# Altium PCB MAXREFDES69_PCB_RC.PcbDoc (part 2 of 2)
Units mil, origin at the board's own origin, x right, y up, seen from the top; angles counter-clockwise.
Board outline 2598.42 x 2244.09 mil, 6 copper layers (Top Layer, Mid-Layer 1, Mid-Layer 2, Mid-Layer 3, Mid-Layer 4, Bottom Layer); 103 components, 84 nets, 415 pads, 171 vias.
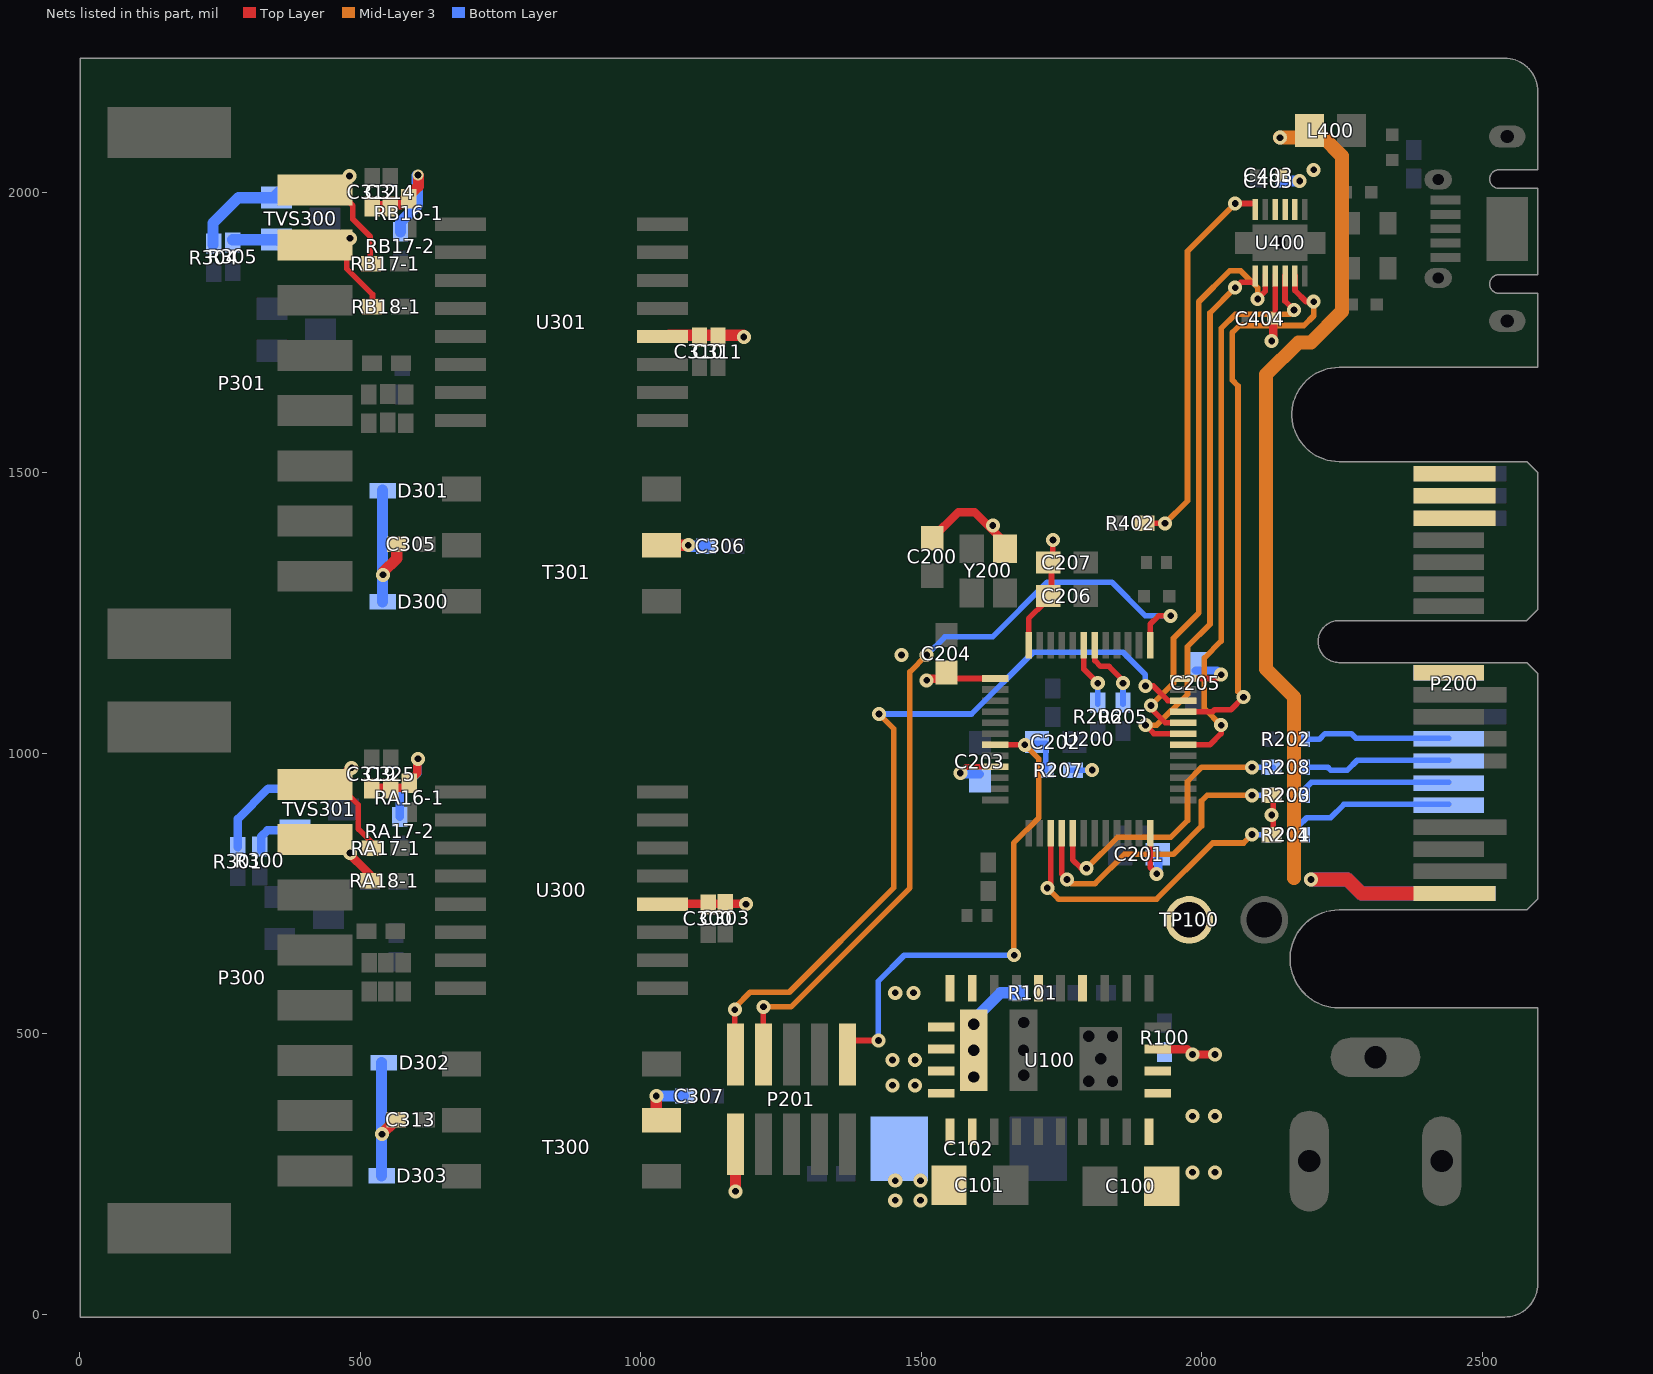
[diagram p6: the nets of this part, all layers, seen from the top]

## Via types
v1: diameter 25, hole 12, Top Layer to Bottom Layer, 164 vias
v2: diameter 20, hole 12, Top Layer to Bottom Layer, 3 vias
v3: diameter 25, hole 12, Top Layer to Bottom Layer, tented top, 3 vias
v4: diameter 25, hole 12, Top Layer to Bottom Layer, tented bottom, 1 vias

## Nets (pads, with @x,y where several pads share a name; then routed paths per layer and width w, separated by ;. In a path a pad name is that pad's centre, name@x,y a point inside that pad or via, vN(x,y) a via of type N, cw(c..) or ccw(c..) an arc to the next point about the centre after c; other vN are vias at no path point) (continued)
NetR203_2: R203.2 U200.16 | length 538.6
  Top Layer w10: U200.16@1750.79,847.83 1750.79,785 v1(1760,775)
  Mid-Layer 3 w10: v1(1760,775) 1767.5,767.5 1810,767.5 1862.5,820 1950,820 2000,870 2000,915 2010,925 v1(2090,925)
  Bottom Layer w10: v1(2090,925) R203.2@2124.41,925 R203.2@2127.5,925
NetR204_2: R204.2 U200.15 | length 548.8
  Top Layer w10: v1(1725,760) 1731.1,766.1 U200.15@1731.1,847.83
  Mid-Layer 3 w10: v1(1725,760) 1745,740 1920,740 2020,840 2075,840 v1(2090,855)
  Bottom Layer w10: v1(2090,855) R204.2@2124.41,855 R204.2@2127.5,855
NetR205_2: R205.2 U200.42 | length 144.2
  Top Layer w10: U200.42@1809.84,1202.17 1809.84,1192.32 1809.84,1165.16 1820,1155 1835,1155 1860,1130 v1(1860,1125)
  Bottom Layer w10: R205.2@1860,1087.5 R205.2@1860,1090.59 v1(1860,1125)
NetR206_2: R206.2 U200.43 | length 125
  Top Layer w10: U200.43@1790.16,1202.17 U200.43@1790.16,1192.32 1790.16,1149.84 v1(1815,1125)
  Bottom Layer w10: R206.2@1815,1087.5 R206.2@1815,1090.59 v1(1815,1125)
NetR208_2: R208.2 U200.17 | length 516.6
  Top Layer w10: U200.17@1770.47,847.83 1770.47,810 1785,795.47 1794.53,795.47 v1(1795,795)
  Mid-Layer 3 w10: v1(1795,795) 1850,850 1945,850 1975,880 1975,950 2000,975 v1(2090,975)
  Bottom Layer w10: v1(2090,975) R208.2@2124.41,975 R208.2@2127.5,975
NetR402_1: R402.1 U400.6 | length 686.9
  Top Layer w10: R402.1@1905.59,1410 v1(1935,1410) ; v1(2060,1980) U400.6@2095.71,1980
  Mid-Layer 3 w10: v1(1935,1410) 1975,1450 1975,1895 v1(2060,1980)
NRST: C202.1 P201.10 R207.1 U200.7 | length 1019.7
  Top Layer w10: P201.10@1369,438 1369,488 v1(1424,488) ; U200.7@1622.83,1015.16 1684.84,1015.16 v1(1685,1015)
  Mid-Layer 3 w10: v1@1665,641 1665,840 1710,885 1710,990 v1(1685,1015)
  Bottom Layer w10: v1(1424,488) 1424,593.9 1470.1,640 v1(1666,640) ; R207.1@1722.5,970 C202.1@1722.5,1015
  Bottom Layer w15: v1(1685,1015) C202.1@1722.5,1015
SPI_#SS: P200.A8 R202.1 | length 275.9
  Bottom Layer w10: R202.1@2172.5,1025 R202.1@2175.59,1025 2210,1025 2220,1035 2266.97,1035 2275,1026.97 P200.A8@2440.95,1026.97
SPI_MISO: P200.A6 R203.1 | length 278.1
  Bottom Layer w10: R203.1@2172.5,925 2174.05,926.55 2195.73,948.23 P200.A6@2440.95,948.23
SPI_MOSI: P200.A7 R208.1 | length 277.8
  Bottom Layer w10: R208.1@2172.5,975 R208.1@2175.59,975 2225,975 2230,970 2260,970 2277.6,987.6 P200.A7@2440.95,987.6
SPI_SCLK: P200.A5 R204.1 | length 299.5
  Bottom Layer w10: R204.1@2172.5,855 2172.5,870 2187.5,885 2230,885 2253.86,908.86 P200.A5@2440.95,908.86
SWCLK: P201.4 U200.37 | length 1470.7
  Top Layer w10: P201.4@1219,435 v1@1219,545 ; U200.37@1908.27,1202.17 1908.27,1230 1923.27,1245 v1(1945,1245)
  Mid-Layer 3 w10: v1(1219,548) 1268,548 1480,760 1480,1145 v1(1510,1175)
  Bottom Layer w10: v1(1510,1175) 1542.5,1207.5 1627.5,1207.5 1725,1305 1840,1305 1900,1245 v1(1945,1245)
SWDIO: P201.2 U200.34 | length 1444.1
  Top Layer w10: v1(1168,543) 1168,516 1169,515 P201.2@1169,435 ; v1(1900,1120) 1913.9,1120 1940,1093.9 U200.34@1977.17,1093.9
  Mid-Layer 3 w10: v1@1169,548 1195,574 1265,574 1451,760 1451,1044 v1(1425,1070)
  Bottom Layer w10: v1(1425,1070) 1590,1070 1700,1180 1860,1180 1900,1140 v1(1900,1120)
TRIGA: P200.B11
TRIGB: P200.A11
USB_CTS: U200.33 U400.11 | length 1016.9
  Top Layer w10: U200.33@1977.17,1074.21 2020,1074.21 2023.29,1077.5 2052.5,1077.5 v1(2075,1100) ; U400.11@2166.57,1850.94 2166.57,1825 2186.57,1805 v1(2200,1805)
  Mid-Layer 3 w10: v1(2075,1100) 2065,1110 2065,1655 2055,1665 2055,1750 2067.5,1762.5 2182.5,1762.5 2200,1780 v1(2200,1805)
USB_RTS: U200.32 U400.8 | length 1044.9
  Top Layer w10: v1(1910,1085) 1910,1079.53 1935,1054.53 U200.32@1967.32,1054.53 U200.32@1977.17,1054.53 ; v1(2100,1810) 2113.43,1823.43 U400.8@2113.43,1850.94
  Mid-Layer 3 w10: v1(1910,1085) 1950,1125 1950,1205 1995,1250 1995,1805 2050,1860 2070,1860 2100,1830 v1(2100,1810)
USB_RX: U200.30 U400.10 | length 1024.4
  Top Layer w10: U200.30@1977.17,1015.16 2015,1015.16 2035,1035.16 v1(2035,1050) ; U400.10@2148.86,1850.94 2148.86,1806.14 v1(2165,1790)
  Mid-Layer 3 w10: v1(2035,1050) 2005,1080 2005,1170 2035,1200 2035,1757.5 2060,1782.5 2157.5,1782.5 v1(2165,1790)
USB_TX: U200.31 U400.7 | length 992
  Top Layer w10: v1(1900,1050) 1915,1035 1915,1034.84 1967.32,1034.84 U200.31@1977.17,1034.84 ; v1(2060,1830) 2060.5,1830 2070,1839.5 2094.71,1839.5 2095.71,1840.5 U400.7@2095.71,1850.94
  Mid-Layer 3 w10: v1(1900,1050) 1920,1050 1975,1105 1975,1190 2015,1230 2015,1785 v1(2060,1830)
V1: C313.1 C319.2 C325.2 D302.2 D303.2 RA16-1.2 RA17-2.2 | length 468.6
  Top Layer w15: C319.2@526.41,938.59 RA16-1.2@584.59,938.59 ; RA16-1.2@583,946 602,965 v1@602,991
  Top Layer w20: v1(539,321) 539,322 C313.1@560,343
  Bottom Layer w15: D302.2@538.17,448.17 D302.2@540,450 ; RA17-2.2@571,886.59 571,933 602,964 602,994 v1@604,992
  Bottom Layer w20: D303.2@538.17,247 D302.2@538.17,448.17
  other v1: 603,990
V2: C305.1 C312.2 C314.2 D300.2 D301.2 RB16-1.2 RB17-2.2 | length 494.2
  Top Layer w20: C312.2@522,1974.41 C314.2@554,1974.41 558.59,1979 572,1979 604,2011 v2@604,2030 ; v1@541,1323 565.41,1347.41 C305.1@565.41,1373 ; RB16-1.2@585,1990 RB16-1.2@588,1990
  Bottom Layer w10: D300.2@540.17,1270 540.17,1267.17 D300.2@540.33,1267
  Bottom Layer w20: D300.2@540.17,1270 D301.2@540.17,1469 ; RB17-2.2@572,1929.59 572,1947 602,1977 v2@602,2030
  other v1: 541,1318
  other v2: 603,2031
V5V: C100.1 L400.2 P200.A1 P200.B1 R100.2 TP100.1 U100.1 U100.2 U100.3 U100.8 U100.10 U100.28 | length 2146.4
  Top Layer w15: U100.3@1921.91,472.69 1974.31,472.69 v1(1984,463) v1(2024,463)
  Top Layer w25: v1(2195,775) 2260,775 2285,750 P200.B1@2432.17,750
  Mid-Layer 3 w25: v1(2140,2097.5) 2217.5,2097.5 2250,2065 2250,1787.5 2195,1732.5 2172.5,1732.5 2115,1675 2115,1150 2165,1100 2165,778
  Bottom Layer w10: R100.2@1934,470.5 v1@1979,470.5
  Bottom Layer w25: v1(2195,775) 2260,775 2285,750 P200.A1@2432.17,750
  other v1: 1984,253 2024,253 1984,353 2024,353
V24V: P200.B16 P200.B17 P200.B18
VDD_S: C101.1 C102.1 C200.1 C201.1 C203.1 C204.1 C205.1 C206.1 C207.1 C300.2 C303.2 C306.1 C307.1 C310.2 C311.2 C403.1 C404.1 C405.1 P201.1 R101.2 R200.2 R201.2 R207.2 T300.2 T301.2 U100.13 U100.14 U100.15 U100.16 U100.17 U100.18 U100.19 U100.20 U100.29 U100.32 U100.33 U100.34 U200.1 U200.9 U200.24 U200.36 U200.48 U300.4 U301.4 U400.2 U400.3 U400.4 U400.9 Y200.4 | length 1656.9
  Top Layer w10: C204.1@1545,1132.5 1545.77,1133.27 U200.1@1622.83,1133.27 ; v1(1570,965) 1580,975 1580,975.79 U200.9@1622.83,975.79 ; U200.48@1691.73,1202.17 1691.73,1240 1721.73,1270 1722.5,1270 1732.5,1280 1732.5,1335 1735,1335 v1(1735,1380) ; U200.24@1908.27,847.83 1908.27,796.73 v1(1920,785) ; U200.36@1977.17,1133.27 2028.27,1133.27 v1(2035,1140) ; v1(2125,890) v1@2127.5,890 ; R201.2@2127.5,855 v1@2127.5,890 ; R200.2@2127.5,925 v1@2127.5,890 ; C404.1@2127.5,1770 2127.5,1771.36 2131.14,1775 U400.9@2131.14,1850.94
  Top Layer w15: U300.4@1046,732 v3@1190,732 ; v1(1510,1130) 1510,1132.5 C204.1@1545,1132.5 ; C200.1@1520,1383.46 1566.54,1430 1595.53,1430 Y200.4@1649.53,1376 ; Y200.4@1649.53,1364.37 Y200.4@1649.53,1377.03 ; v1(2125,1735) 2127.5,1740 C404.1@2127.5,1770
  Top Layer w20: v3(1028,389) 1028,355 T300.2@1030,353 ; U301.4@1051,1745 v1@1183,1745 ; T301.2@1055,1374 1058,1371 v1(1085,1371) ; v1(1169,219) P201.1@1169,275
  Bottom Layer w10: v1(1570,965) v1@1572.5,962.5 ; R207.2@1767.5,970 R207.2@1770.59,970 v1(1805,970) ; v1(1920,785) v1@1922.5,787.5
  Bottom Layer w15: v1@1572.5,962.5 C203.1@1605,962.5 ; v1@1922.5,787.5 C201.1@1922.5,820 ; C205.1@1990,1147.5 2027.5,1147.5 v1(2035,1140)
  Bottom Layer w20: v3(1028,389) C307.1@1076,389 ; v1@1083,1371 1085,1369 C306.1@1116.41,1369 ; U100.33@1594,517 1594,525.5 1641.5,573 R101.2@1673.41,573 R101.2@1676.5,573 ; C405.1@2142.5,2020 v1(2175,2020)
  other v1: 1454,203 1499,203 1454,238 1499,238 1449,408 1489,408 1449,453 1489,453 1454,573 1486.5,573 1465,1175 1628,1406 1184,1742 2200,2040
  other v3: 1188,731
Y1: P300.1 R301.2 RA17-1.2 TVS301.1 | length 429
  Top Layer w8: RA17-1.2@520.41,831 RA17-1.2@520.41,841.59
  Top Layer w10: P300.1@474,931 497,908 497,865 RA17-1.2@520.41,841.59
  Top Layer w15: P300.1@454,952 P300.1@458,956 ; P300.1@471,963 v1@483.5,975.5
  Bottom Layer w15: R301.2@282,832.59 282,883 336,937 TVS301.1@382,937 ; TVS301.1@383.69,937.4 448.4,937.4 v1@483,972
  other v1: 485,974
Y2: P301.1 R304.2 RB17-1.2 TVS300.1 | length 453.8
  Top Layer w10: P301.1@466,1997 487,1976 487,1952 518,1921 RB17-1.2@518,1886
  Bottom Layer w20: R304.2@238,1906 238,1945 283.4,1990.4 TVS300.1@350.69,1990.4 ; TVS300.1@347,1992 357,2002 454,2002 v1@482,2030
  other v1: 481,2029
Z1: P300.2 R300.2 RA18-1.2 TVS301.2 | length 247.3
  Top Layer w15: P300.2@473.41,828 RA18-1.2@517.41,784
  Bottom Layer w15: R300.2@324,827 324,852 334.6,862.6 TVS301.2@383.69,862.6 ; TVS301.2@402,864 402,862.6 443.4,862.6 v1@481,825
  other v1: 482,822
Z2: P301.2 R305.2 RB18-1.2 TVS300.2 | length 316.8
  Top Layer w8: RB18-1.2@521.41,1796 520,1796 RB18-1.2@522,1798
  Top Layer w10: P301.2@476,1890 476,1864 522,1818 RB18-1.2@522,1798
  Bottom Layer w20: R305.2@273,1915 R305.2@273.6,1915.6 ; R305.2@273,1915.6 TVS300.2@350.69,1915.6 ; TVS300.2@354,1914 v1@477,1914
  other v1: 482,1918
pads on no net: P200.A3 P200.A12 P200.A13 P200.A14 P200.A15 P200.B3 P200.B12 P200.B13 P200.B14 P200.B15 P201.6 P201.8 P300.9 P300.10 P301.9 P301.10 P400.4 T300.1@1055.85,149.15 T301.1@1055.85,1174.15 U100.11 U100.12 U200.2 U200.3 U200.4 U200.6 U200.18 U200.19 U200.25 U200.26 U200.28 U200.29 U200.40 U200.41 U200.45 U200.46 Y200.1

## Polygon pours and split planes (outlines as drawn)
GNDB on Mid-Layer 4 "Mid-Layer 4-ISO_GND" (solid, remove dead copper, pour order 45): 25,25 2568,18 2568,516 2138,516 2138,88 702,87 698,2228 1120,600 1120,1334 1119.97,1440 1090,1440 1090,2225 25,2225
GND_S on Mid-Layer 4 "Mid-Layer 4-GND_S" (solid, remove dead copper, pour order 46): 1047,170 2040,178 2043,552 2222,750 2220,749 2575,750 2575,1140 2245,1140 2244.97,1140 2240.53,1140.14 2236.1,1140.59 2231.71,1141.35 2227.39,1142.41 2223.16,1143.77 2219.02,1145.42 2215.02,1147.36 2211.16,1149.57 2207.46,1152.04 2203.94,1154.77 2200.63,1157.74 2197.52,1160.93 2194.65,1164.33 2192.02,1167.92 2189.65,1171.68 2187.55,1175.6 2185.73,1179.66 2184.19,1183.84 2182.95,1188.11 2182.01,1192.46 2181.37,1196.87 2181.05,1201.3 2181.03,1205.75 2181.33,1210.19 2181.93,1214.6 2182.84,1218.96 2184.05,1223.24 2185.56,1227.42 2187.35,1231.5 2189.43,1235.43 2191.77,1239.21 2194.38,1242.82 2197.23,1246.24 2200.31,1249.45 2203.6,1252.44 2207.1,1255.19 2210.78,1257.7 2214.62,1259.93 2218.62,1261.9 2222.74,1263.58 2226.96,1264.97 2231.28,1266.06 2235.66,1266.85 2240.08,1267.33 2244.53,1267.5 2244.97,1267.5 2575,1267.5 2575,1500 2242.5,1500 2234.83,1500.27 2227.19,1501.07 2219.63,1502.4 2212.18,1504.26 2204.88,1506.63 2197.76,1509.51 2190.86,1512.88 2184.21,1516.71 2177.84,1521.01 2171.79,1525.74 2166.09,1530.87 2160.75,1536.4 2155.82,1542.28 2151.31,1548.49 2147.24,1555 2143.63,1561.78 2140.51,1568.79 2137.88,1576.01 2135.77,1583.39 2134.17,1590.9 2133.1,1598.5 2132.57,1606.16 2132.57,1613.84 2133.1,1621.5 2134.17,1629.1 2135.77,1636.61 2137.88,1643.99 2140.51,1651.21 2143.63,1658.22 2147.24,1665 2151.31,1671.51 2155.82,1677.72 2160.75,1683.6 2166.09,1689.13 2171.79,1694.26 2177.84,1698.99 2184.21,1703.29 2190.86,1707.12 2197.76,1710.49 2204.88,1713.37 2212.18,1715.74 2219.63,1717.6 2227.19,1718.93 2234.83,1719.73 2242.5,1720 2575,1720 2575,2195 2550,2220 2546,2220 1050,2223
V5V on Mid-Layer 2 "Mid-Layer 2-V5V" (solid, remove dead copper, pour order 40): 1890,700 1890,176 2044,176 2044,550 2126,632 2125,675 2200,750 2275,750 2275,800 2125,800 2025,700
VDD_S on Mid-Layer 2 "Mid-Layer 2-VDD_S" (solid, remove dead copper, pour order 42): 1750,180 1750,725 1950,725 1950,825 2575,825 2575,1140 2245,1140 2244.97,1140 2240.53,1140.14 2236.1,1140.59 2231.71,1141.35 2227.39,1142.41 2223.16,1143.77 2219.02,1145.42 2215.02,1147.36 2211.16,1149.57 2207.46,1152.04 2203.94,1154.77 2200.63,1157.74 2197.52,1160.93 2194.65,1164.33 2192.02,1167.92 2189.65,1171.68 2187.55,1175.6 2185.73,1179.66 2184.19,1183.84 2182.95,1188.11 2182.01,1192.46 2181.37,1196.87 2181.05,1201.3 2181.03,1205.75 2181.33,1210.19 2181.93,1214.6 2182.84,1218.96 2184.05,1223.24 2185.56,1227.42 2187.35,1231.5 2189.43,1235.43 2191.77,1239.21 2194.38,1242.82 2197.23,1246.24 2200.31,1249.45 2203.6,1252.44 2207.1,1255.19 2210.78,1257.7 2214.62,1259.93 2218.62,1261.9 2222.74,1263.58 2226.96,1264.97 2231.28,1266.06 2235.66,1266.85 2240.08,1267.33 2244.53,1267.5 2244.97,1267.5 2575,1267.5 2575,1500 2242.5,1500 2234.83,1500.27 2227.19,1501.07 2219.63,1502.4 2212.18,1504.26 2204.88,1506.63 2197.76,1509.51 2190.86,1512.88 2184.21,1516.71 2177.84,1521.01 2171.79,1525.74 2166.09,1530.87 2160.75,1536.4 2155.82,1542.28 2151.31,1548.49 2147.24,1555 2143.63,1561.78 2140.51,1568.79 2137.88,1576.01 2135.77,1583.39 2134.17,1590.9 2133.1,1598.5 2132.57,1606.16 2132.57,1613.84 2133.1,1621.5 2134.17,1629.1 2135.77,1636.61 2137.88,1643.99 2140.51,1651.21 2143.63,1658.22 2147.24,1665 2151.31,1671.51 2155.82,1677.72 2160.75,1683.6 2166.09,1689.13 2171.79,1694.26 2177.84,1698.99 2184.21,1703.29 2190.86,1707.12 2197.76,1710.49 2204.88,1713.37 2212.18,1715.74 2219.63,1717.6 2227.19,1718.93 2234.83,1719.73 2242.5,1720 2575,1720 2575,2220 2076,2220 2079,2222 1032,2222 1032,180
ISO_24V on Mid-Layer 2 "GND" (solid, pour order 29): 341,281 342,22 2560,22 2558,514 2136,514 2136,92 702,91 702,281
V1 on Mid-Layer 2 "Top Layer-No Net" (solid, pour order 26): 328,1136.05 698,1136.05 697,297 329,298 330,1136.05 331,1137
V2 on Mid-Layer 2 "Top Layer-No Net" (solid, pour order 25): 325,2178.93 695,2178.93 694,1232 326,1233.13 327,2178.93 328,2180
GNDB on Mid-Layer 1 "Mid-Layer 1-ISO_GND 1" (solid, remove dead copper, pour order 34): 25,25 2564,26 2566,520 2144,516 2140,96 686,100 689,2225 1118,600 1120,1440 1092.5,1440 1092.5,2225 25,2225
GND_S on Mid-Layer 1 "Mid-Layer 1-GND_S" (solid, remove dead copper, pour order 33): 1042,186 1154,182 2040,182 2040,625 2175,750 2575,750 2575,1140 2245,1140 2244.97,1140 2240.53,1140.14 2236.1,1140.59 2231.71,1141.35 2227.39,1142.41 2223.16,1143.77 2219.02,1145.42 2215.02,1147.36 2211.16,1149.57 2207.46,1152.04 2203.94,1154.77 2200.63,1157.74 2197.52,1160.93 2194.65,1164.33 2192.02,1167.92 2189.65,1171.68 2187.55,1175.6 2185.73,1179.66 2184.19,1183.84 2182.95,1188.11 2182.01,1192.46 2181.37,1196.87 2181.05,1201.3 2181.03,1205.75 2181.33,1210.19 2181.93,1214.6 2182.84,1218.96 2184.05,1223.24 2185.56,1227.42 2187.35,1231.5 2189.43,1235.43 2191.77,1239.21 2194.38,1242.82 2197.23,1246.24 2200.31,1249.45 2203.6,1252.44 2207.1,1255.19 2210.78,1257.7 2214.62,1259.93 2218.62,1261.9 2222.74,1263.58 2226.96,1264.97 2231.28,1266.06 2235.66,1266.85 2240.08,1267.33 2244.53,1267.5 2244.97,1267.5 2575,1267.5 2575,1500 2242.5,1500 2234.83,1500.27 2227.19,1501.07 2219.63,1502.4 2212.18,1504.26 2204.88,1506.63 2197.76,1509.51 2190.86,1512.88 2184.21,1516.71 2177.84,1521.01 2171.79,1525.74 2166.09,1530.87 2160.75,1536.4 2155.82,1542.28 2151.31,1548.49 2147.24,1555 2143.63,1561.78 2140.51,1568.79 2137.88,1576.01 2135.77,1583.39 2134.17,1590.9 2133.1,1598.5 2132.57,1606.16 2132.57,1613.84 2133.1,1621.5 2134.17,1629.1 2135.77,1636.61 2137.88,1643.99 2140.51,1651.21 2143.63,1658.22 2147.24,1665 2151.31,1671.51 2155.82,1677.72 2160.75,1683.6 2166.09,1689.13 2171.79,1694.26 2177.84,1698.99 2184.21,1703.29 2190.86,1707.12 2197.76,1710.49 2204.88,1713.37 2212.18,1715.74 2219.63,1717.6 2227.19,1718.93 2234.83,1719.73 2242.5,1720 2575,1720 2575,2220 2058,2220 2055,2222 1042,2222
GND_S on Bottom Layer "Bottom Layer-GND_S" (solid, remove dead copper, pour order 32): 2578,2221 2565,2221.03 1055,2224 1049,176.99 2043.26,175.8 2044,563 2280,794.26 2280,1131.14 2245,1131.14 2244.97,1131.14 2240.53,1131.28 2236.1,1131.72 2231.71,1132.47 2227.39,1133.52 2223.16,1134.87 2219.02,1136.51 2215.02,1138.43 2211.16,1140.62 2207.46,1143.07 2203.94,1145.77 2200.63,1148.71 2197.52,1151.87 2194.65,1155.24 2192.02,1158.8 2189.65,1162.53 2187.55,1166.42 2185.73,1170.44 2184.19,1174.57 2182.95,1178.81 2182.01,1183.12 2181.37,1187.48 2181.05,1191.88 2181.03,1196.29 2181.33,1200.69 2181.93,1205.05 2182.84,1209.37 2184.05,1213.61 2185.56,1217.76 2187.35,1221.79 2189.43,1225.69 2191.77,1229.44 2194.38,1233.02 2197.23,1236.4 2200.31,1239.59 2203.6,1242.55 2207.1,1245.27 2210.78,1247.75 2214.62,1249.97 2218.62,1251.92 2222.74,1253.58 2226.96,1254.96 2231.28,1256.04 2235.66,1256.82 2240.08,1257.3 2244.53,1257.47 2244.97,1257.47 2280,1257.47 2280,1487.83 2242.5,1487.83 2234.83,1488.1 2227.19,1488.89 2219.63,1490.21 2212.18,1492.05 2204.88,1494.4 2197.76,1497.25 2190.86,1500.59 2184.21,1504.39 2177.84,1508.64 2171.79,1513.33 2166.09,1518.42 2160.75,1523.89 2155.82,1529.72 2151.31,1535.87 2147.24,1542.32 2143.63,1549.04 2140.51,1555.99 2137.88,1563.14 2135.77,1570.45 2134.17,1577.89 2133.1,1585.43 2132.57,1593.02 2132.57,1600.62 2133.1,1608.21 2134.17,1615.74 2135.77,1623.19 2137.88,1630.5 2140.51,1637.65 2143.63,1644.6 2147.24,1651.31 2151.31,1657.76 2155.82,1663.92 2160.75,1669.75 2166.09,1675.22 2171.79,1680.31 2177.84,1684.99 2184.21,1689.25 2190.86,1693.05 2197.76,1696.38 2204.88,1699.23 2212.18,1701.59 2219.63,1703.43 2227.19,1704.75 2234.83,1705.54 2242.5,1705.81 2575,1705.81 2575,2106 2578,2104
GNDB on Bottom Layer "GND" (solid, pour order 27): 22,586 19.01,2218.01 701,2221 702,98 2134,98 2134,514 2138,518 2564,518 2564,26 2562,24 20,23 20,582
GND_F on Bottom Layer "Bottom Layer-GND_F" (solid, remove dead copper, pour order 31): 2110,1291 2368,1291 2368,1407 2476,1408 2476,1500 2370,1499 2110,1499
VDD_S on Mid-Layer 3 "Mid-Layer 2-VDD_S" (solid, remove dead copper, pour order 41): 1745,182 1745,727 1945,727 1945,827 2570,827 2570,1142 2240,1142 2239.97,1142 2235.53,1142.14 2231.1,1142.59 2226.71,1143.35 2222.39,1144.41 2218.16,1145.77 2214.02,1147.42 2210.02,1149.36 2206.16,1151.57 2202.46,1154.04 2198.94,1156.77 2195.63,1159.74 2192.52,1162.93 2189.65,1166.33 2187.02,1169.92 2184.65,1173.68 2182.55,1177.6 2180.73,1181.66 2179.19,1185.84 2177.95,1190.11 2177.01,1194.46 2176.37,1198.87 2176.05,1203.3 2176.03,1207.75 2176.33,1212.19 2176.93,1216.6 2177.84,1220.96 2179.05,1225.24 2180.56,1229.42 2182.35,1233.5 2184.43,1237.43 2186.77,1241.21 2189.38,1244.82 2192.23,1248.24 2195.31,1251.45 2198.6,1254.44 2202.1,1257.19 2205.78,1259.7 2209.62,1261.93 2213.62,1263.9 2217.74,1265.58 2221.96,1266.97 2226.28,1268.06 2230.66,1268.85 2235.08,1269.33 2239.53,1269.5 2239.97,1269.5 2570,1269.5 2570,1502 2237.5,1502 2229.83,1502.27 2222.19,1503.07 2214.63,1504.4 2207.18,1506.26 2199.88,1508.63 2192.76,1511.51 2185.86,1514.88 2179.21,1518.71 2172.84,1523.01 2166.79,1527.74 2161.09,1532.87 2155.75,1538.4 2150.82,1544.28 2146.31,1550.49 2142.24,1557 2138.63,1563.78 2135.51,1570.79 2132.88,1578.01 2130.77,1585.39 2129.17,1592.9 2128.1,1600.5 2127.57,1608.16 2127.57,1615.84 2128.1,1623.5 2129.17,1631.1 2130.77,1638.61 2132.88,1645.99 2135.51,1653.21 2138.63,1660.22 2142.24,1667 2146.31,1673.51 2150.82,1679.72 2155.75,1685.6 2161.09,1691.13 2166.79,1696.26 2172.84,1700.99 2179.21,1705.29 2185.86,1709.12 2192.76,1712.49 2199.88,1715.37 2207.18,1717.74 2214.63,1719.6 2222.19,1720.93 2229.83,1721.73 2237.5,1722 2570,1722 2570,2222 2071,2222 2074,2224 1027,2224 1027,182
V5V on Mid-Layer 3 "Mid-Layer 3-V5V" (solid, remove dead copper, pour order 44): 1894,702 1894,218 2046,218 2047,563 2240,760 2241,794 1896,794
ISO_24V on Mid-Layer 3 "GND" (solid, pour order 30): 344,392 344,22 2565.67,22 2568,514 2140,514 2140,90 696,91 696,391
VDD_S on Mid-Layer 3 "Mid-Layer 3-VDD_S" (solid, remove dead copper, pour order 43): 1599,178 1599,423 1619,423 1619,553 1599,553 1599,605.5 1429,605.5 1429,178
ISO_24V on Top Layer "GND" (solid, pour order 28): 344,390 344,20 2562,20 2560,512 2138,512 2138,90 508,90 509,197 508,389
GND_S on Top Layer "Top Layer-GND_S" (solid, remove dead copper, pour order 39): 1619,178 1879,178 1880,550 1932,550 1932,604 1818,604 1818,510 1734,510 1734,382.71 1619,382.71
GNDB on Top Layer "GND" (solid, pour order 24): 346,520 346,420 518,420 518,520 346,520
V5V on Top Layer "Top Layer-V5V 1" (solid, remove dead copper, pour order 38): 1894,178 2044,178 2044,496.46 1894,496.46
VDD_S on Top Layer "Top Layer-VDD_S" (solid, remove dead copper, pour order 36): 1599,178 1599,423 1619,423 1619,553 1599,553 1599,605.5 1429,605.5 1429,178
V5V on Top Layer "Top Layer-V5V" (solid, remove dead copper, pour order 35): 1976,618 1975,400 2035,400 2035,550 2126,642 2125,675 2200,750 2274,750 2274,796 2122,796 2025,700 1696,700 1696,554 1802,554 1802,618
V24V on Top Layer "Top Layer-V24V" (solid, remove dead copper, pour order 37): 2372,1509 2372,1508.64 2372,1410 2372,1412 2371,1411.7 2472,1411.7 2472,1510 2374,1509

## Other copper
Top Layer:
  region net VDD_S: 2129,2057.5 2129,1953 2169,1953 2169,2005 2215,2005 2215,2057.5 2129,2057.5
  region net V5V: 2125,2145 2125,2075 2215,2075 2215,2145 2125,2145
  region net NetC400_1: 2245,2145 2245,2035 2355,2035 2355,2070 2310,2070 2310,2145 2245,2145
  text "COMPONENT SIDE" at 475,2850 h50
Mid-Layer 1:
  text "LAYER 2 GND_F, GND_S, ISO_GND" at 475,2850 h50
Mid-Layer 2:
  text "LAYER 3  24V, 3V3V, V5V, VDD_S" at 375,2850 h50
Mid-Layer 3:
  text "LAYER 4 ISO_24V, V24V, V5V, VDD_S, SIGNALS" at 375,2850 h40
Mid-Layer 4:
  text "LAYER 5 ISO_GND, GND_F, GND_S" at 500,2850 h50
Bottom Layer:
  region net VDD_S: 1402,388 1402,188 1522,188 1522,388 1402,388
  text "SOLDER SIDE SIGNALS" at 475,2850 h50
Multi-Layer:
  drawing of 3777 lines, arcs and shapes, not listed
  text "MAXREFDES69" at 812.01,4012.01 h90
  text "uPLC IO Card - RS485 Board" at 612.01,3862.01 h60
  text "REV" at 2350,3675 h35
  text "P/N: EPCBREFDES69" at 225,3575 h90
  text "C" at 2375,3525 h75
  text "LAYER" at 100,2925 h35
  text "DATE:" at 100,2700 h35
  text "ALL UNITS ARE IN 0.001\"" at 1325,2625 h50
  text "1.0\"" at 2075,-525 h50

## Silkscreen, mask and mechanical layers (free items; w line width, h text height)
Top Overlay:
  drawing of 3667 lines, arcs and shapes, not listed
  text "TOP SILKSCREEN" at 425,2850 h50
  text "Y" at 432,2044 h30
  text "1" at 2377,2021 h25
  text "Z" at 432,1940 h30
  text "MAXREFDES69#" at 1451,1916 h35
  text "uPLC Isolated RS-485" at 1369,1843 h35
  text "B" at 432,1841 h30
  text "5" at 2365,1770 h25
  text "A" at 432,1743 h30
  text "TERM" at 367,1645 h30
  text "GND" at 380,1546 h30
  text "B18" at 2214,1482 h25
  text "GND" at 377,1447 h30
  text "GND" at 379,1347 h30
  text "1" at 1575,1130 h25
  text "Y" at 422,980 h30
  text "Z" at 422,879 h30
  text "B" at 422,782 h30
  text "B1" at 2241,741 h25
  text "A" at 422,682 h30
  text "TERM" at 363,583 h30
  text "2" at 1137,528 h25
  text "10" at 1366,528 h25
  text "GND" at 384,488 h30
  text "24V" at 392,388 h30
  text "1" at 1959,368 h25
  text "+24V" at 2280,365 h25 r270
  text "PGND" at 2495,355 h25 r270
  text "24V" at 388,291 h30
  text "9" at 1399,198 h25
  text "1" at 1134,193 h25
Bottom Overlay:
  text "BOTTOM SILKSCREEN" at 750,2850 h50
  text "A18" at 2356,1475 h25
  text "A1" at 2250,750 h25
  text "+" at 1425,214 h25
  text "P/N: EPCBREFDES69" at 465,101 h30
  text "06/16 ST" at 228,41 h30
  text "REV-C" at 457,36 h30
Top Solder:
  region: 2598.42,1166.69 2283.46,1166.69 2283.46,725.75 2598.42,725.75 2598.42,1166.69
  region: 2598.42,1524.96 2283.46,1524.96 2283.46,1241.5 2598.42,1241.5 2598.42,1524.96
  text "TOP SOLDERMASK" at 425,2850 h50
Bottom Solder:
  region: 2598.42,1166.69 2283.46,1166.69 2283.46,725.75 2598.42,725.75 2598.42,1166.69
  region: 2598.42,1524.96 2283.46,1524.96 2283.46,1241.5 2598.42,1241.5 2598.42,1524.96
  text "BOTTOM SOLDERMASK" at 425,2850 h50
Mechanical 1:
  lines w1: 2255.1,551.18 2255.13,551.18 ; 2255.09,1131.1 2255.12,1131.1 ; 2255.1,1692.91 2255.13,1692.91 ; 2432.26,551.18 2432.29,551.18 ; 2432.26,1692.91 2432.29,1692.91 ; 2363.37,1525 2363.4,1525 ; 2422.42,725.75 2422.44,725.75 ; 2422.42,1166.69 2422.45,1166.69 ; 2452.94,1241.53 2452.96,1241.53 ; 2540.53,1858.27 2540.56,1858.27 ; 2574.98,1824.81 2575.01,1824.81 ; 2574.98,1858.27 2575.01,1858.27 ; 2609.43,551.18 2609.46,551.18 ; 2609.42,1111.41 2609.45,1111.41
  lines w8: 1,-5 2540.37,-5 ccw(c2540.37,54.06) 2599.42,54.06 2599.42,546.18 2245.09,546.18 cw(c2245.1,633.47) 2245.1,720.75 2579.74,720.75 2599.42,740.43 2599.42,1142.01 2579.74,1161.69 2245.09,1161.69 cw(c2245.09,1199.09) 2245.09,1236.49 2579.74,1236.49 2599.42,1256.18 2599.42,1500.27 2579.74,1519.96 2245.09,1519.96 cw(c2245.1,1603.94) 2245.1,1687.91 2599.42,1687.91 2599.42,1819.8 2530.53,1819.8 cw(c2530.33,1836.53) 2530.53,1853.27 2599.42,1853.27 2599.42,2006.81 2530.53,2006.81 cw(c2530.32,2023.54) 2530.52,2040.27 2599.42,2040.27 2599.42,2180.04 ccw(c2540.37,2180.03) 2540.37,2239.09 1,2239.09 1,-5
  lines w10: 2592.13,17.3 2592.15,17.3
Mechanical 13:
  drawing of 442 lines, arcs and shapes, not listed
  text "NOTES: UNLESS OTHERWISE SPECIFIED" at 4250,3331 h100
  text "1. FABRICATE USING PROVIDED GERBER FILES PER LATEST REVISION" at 4350,3181 h50
  text "OF IPC-A-600 UNLESS OTHERWISE NOTED." at 4475,3031 h50
  text "2: MATERIAL: RoHS COMPLIANT FR-408 OR SIMILAR LAMINATE MATERIAL" at 4350,2881 h50
  text "DRILL & MECHANICALS" at 475,2846 h50
  text "WITH Tg>=170 AND COMPATIBLE WITH LEAD-FREE SOLDERING PROCESS." at 4475,2731 h50
  text "3. BOARD DIMENSIONS: 2.598\"x2.244\" (66mmx57mm) +/- 0.010\"." at 4350,2581 h50
  text "BOARD THICKNESS: 0.062\"" at 4475,2431 h50
  text "66.0mm" at 1145.86,2328.5 h50
  text "4. LAYERS: 6. SEE LAYER STACKUP CHART BELOW." at 4350,2281 h50
  text "R0.4mm" at 2056,2148.73 h50
  text "5. MINIMUM TRACE/SPACING: 8 MILS/4 MILS." at 4350,2131 h50
  text "6. COPPER CLAD FINISH: 1oz MINIMUM ON OUTER LAYERS AND 1oz ON INNER LAYERS." at 4350,1981 h50
  text "0.85mm" at 2805,1896 h50
  text "7. SURFACE MOUNT PADS: 632." at 4350,1831 h50
  text "0.85mm" at 3355,1806 h50
  text "1.7mm" at 2262.19,1752.7 h50
  text "R0.4mm" at 2803.84,1716.93 h50
  text "8. SOLDERMASK: GREEN LPI SMOBC." at 4350,1681 h50
  text "4.3mm" at 3000,1570.8 h50
  text "9.0mm" at 2629.93,1566.86 h50
  text "9. LEGENDS: WHITE. DOUBLE-SIDED. NON-CONDUCTIVE EPOXY INK OR EQUIVALENT." at 4350,1556 h50
  text "CLIPPED ALL LEGENDS FROM EXPOSED METAL." at 4500,1406 h50
  text "R2.1mm" at 2667.4,1399.45 h50
  text "R1.0mm" at 2673.3,1289.2 h50
  text "10. PLATING: MUST BE LEAD FREE AND RoHS COMPLIANT." at 4350,1256 h50
  text "1.9mm" at 3220.48,1169.23 h50
  text "9.0mm" at 2633.86,1165.29 h50
  text "11. FINISH: VENDOR SHOULD USE THE MOST ECONOMICAL LEAD FREE AND" at 4375,1106 h50
  text "57.0mm" at -386.82,1080.55 h50
  text "RoHS COMPLIANT PROCESS AVAILABLE OR AS SPECIFIED IN PURCHASE ORDER." at 4525,956 h50
  text "Chamfer details for GOLD FINGERS" at 2740,953 h50
  text "R2.2mm" at 2661.49,797.08 h50
  text "J1 FINGERS: 30 MICRO INCHES HARD GOLD OVER 250 MICRO INCHES NICKEL." at 4525,796 h60
  text "IMMERSION GOLD: REST OF BOARD AREA." at 4537.01,643.01 h50
  text "4.4mm" at 3011.81,606.24 h50
  text "9.0mm" at 2629.93,602.3 h50
  text "12. VENDOR LOGO & DATE CODE IN INK ON BOTTOM SIDE ONLY. DATE CODE FORMAT MUST BE YYWW ONLY." at 4362.01,493.01 h50
  text "13. THRU HOLES: 0.001\" MIN." at 4362.01,343.01 h50
  text "14. TOLERANCES:" at 4362.01,193.01 h50
  text "PLATED-THRU HOLES: +/-0.003\"" at 4562.01,43.01 h50
  text "PATTERN-TO-PATTERN: +/-0.005\"" at 4562.01,-106.99 h50
  text "R1.5mm x 2 places" at 2826.85,-139.92 h50
  text "LEGEND TO LEGEND: +/-0.007\"" at 4562.01,-256.99 h50
  text "SOLDERMASK TO PATTERN: +/-0.005\"." at 4562.01,-356.99 h50
  text "LAYER 1 COMPONENT SIDE" at 4388,-623 h50
  text "1oz" at 5838,-623 h50
  text "PRE-PREG" at 5838,-773 h50
  text "1oz" at 5838,-923 h50
  text "LAYER 2 GND" at 4638,-931 h50
  text "PRE-PREG" at 5838,-1073 h50
  text "LAYER 3 PWR" at 4563,-1223 h50
  text "1oz" at 5838,-1223 h50
  text "1.47mm +/- 0.13mm" at 2701.76,-1354.45 h50
  text "CORE AS NEEDED" at 5838,-1373 h50
  text "1oz" at 5838,-1523 h50
  text "LAYER 4 PWR + SIGNAL" at 4450.01,-1535.99 h50
  text "PRE-PREG" at 5838,-1673 h50
  text "1.40mm +/- 0.20mm" at 2432.07,-1753.93 h50 r90
  text "LAYER 5 GND" at 4638,-1823 h50
  text "1oz" at 5838,-1823 h50
  text "1.57mm +/- 0.13mm" at 2697.82,-1842.51 h50
  text "ACROSS PADS" at 2808.06,-1966.53 h50
  text "PRE-PREG" at 5838,-1973 h50
  text "LAYER 6 SOLDER SIDE" at 4438,-2123 h50
  text "1oz" at 5838,-2123 h50
  text "20" at 2778.58,-2216.57 h50
  text "Chamfer details for GOLD FINGERS" at 1624,-2437 h75
  text "CROSS SECTION DETAIL" at 4288,-2473 h100
Mechanical 14:
  lines w10: 0,0 0,2244.1 2539.37,2244.1 cw(c2539.37,2185.05) 2598.42,2185.05 2598.42,1692.92 2244.09,1692.92 ccw(c2244.09,1608.94) 2244.09,1524.96 2578.74,1524.96 2598.42,1505.28 2598.42,1261.18 2578.74,1241.5 2244.09,1241.5 ccw(c2244.1,1204.1) 2244.1,1166.69 2578.74,1166.69 2598.42,1147.01 2598.42,745.44 2578.74,725.75 2244.09,725.75 ccw(c2244.1,638.47) 2244.1,551.18 2598.42,551.18 2598.42,59.06 cw(c2539.37,59.06) 2539.37,0 0,0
